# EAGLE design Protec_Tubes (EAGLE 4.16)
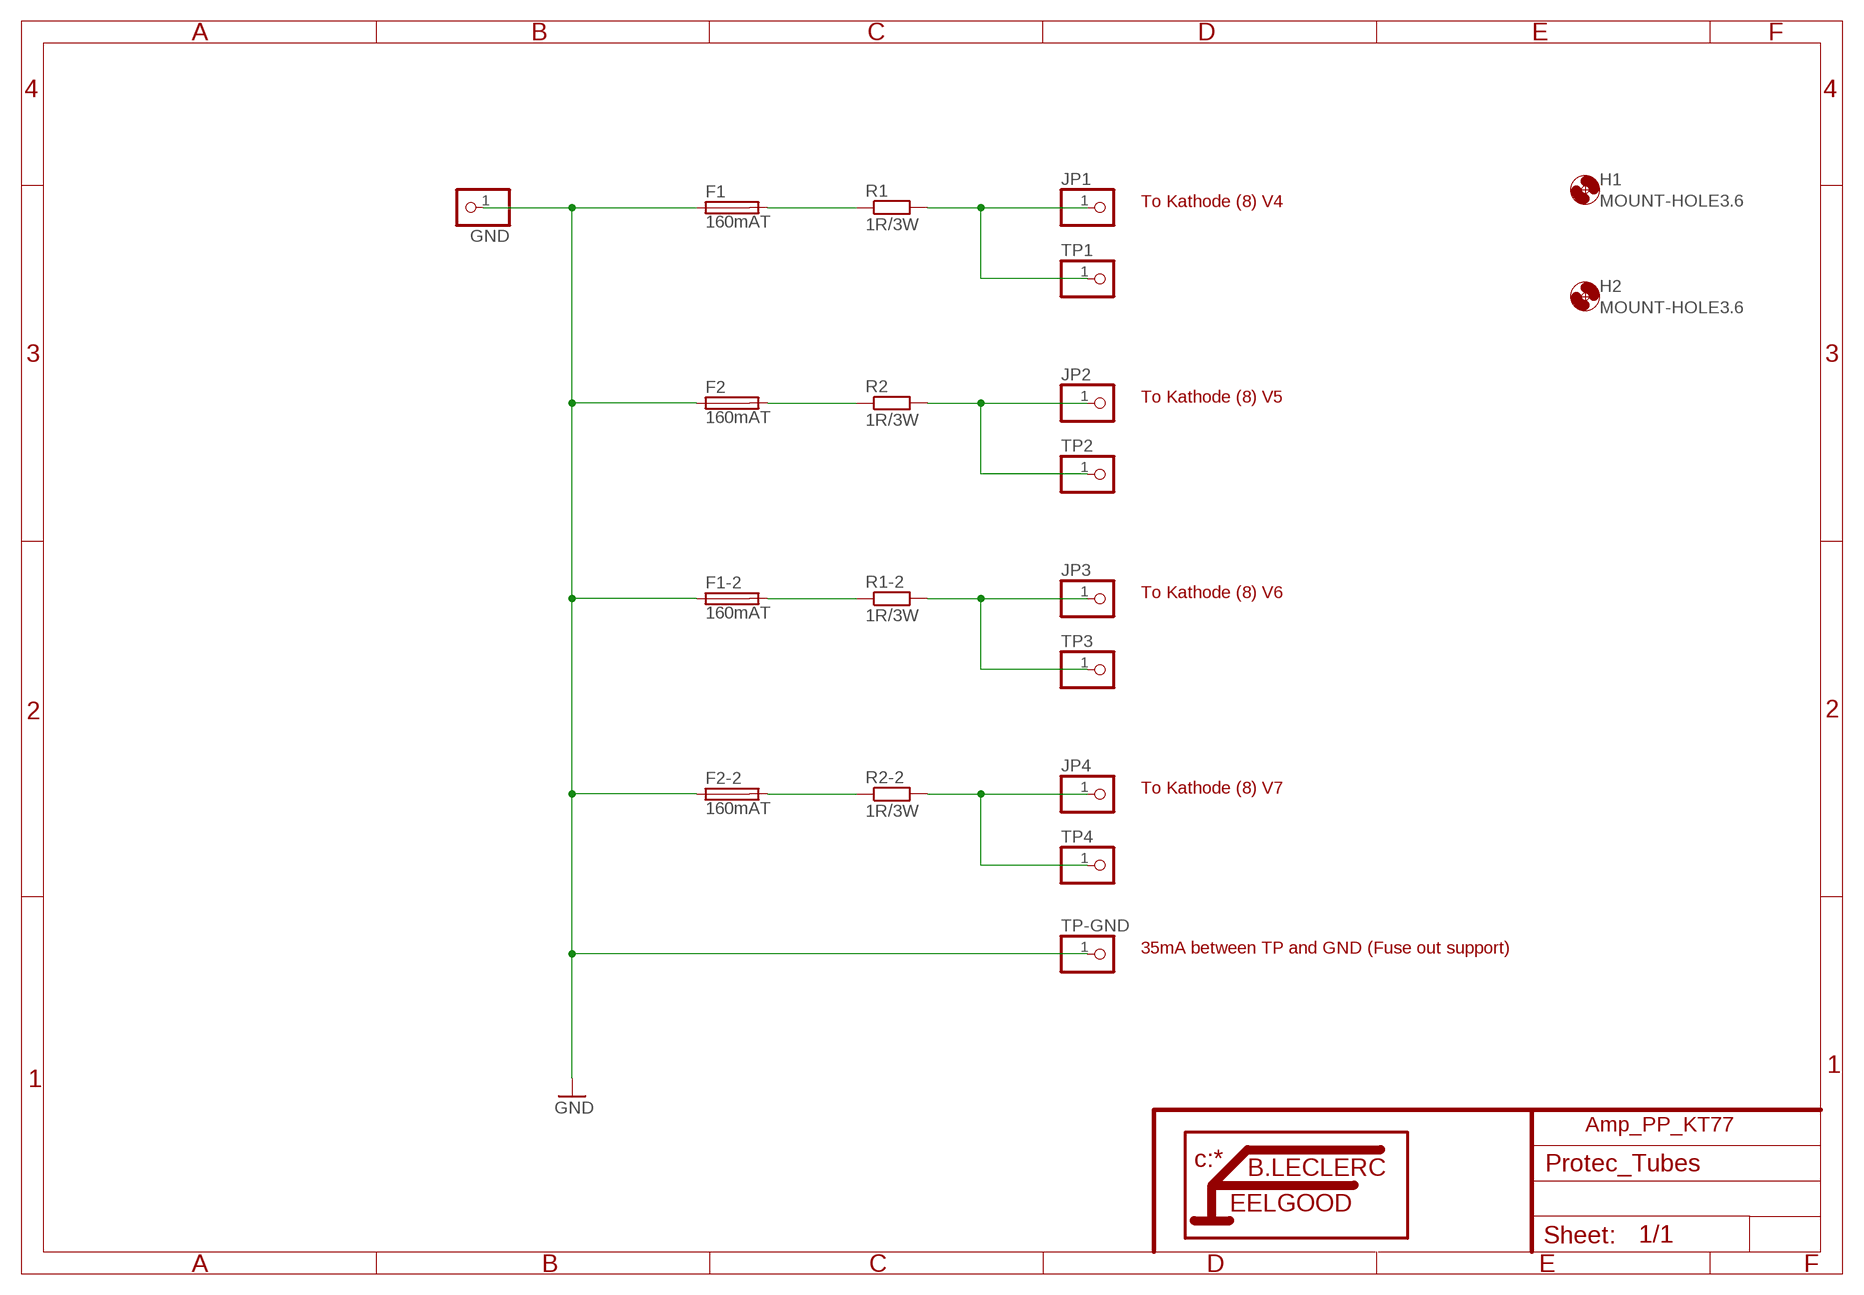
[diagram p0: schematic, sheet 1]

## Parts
F1  160mAT  FUSESH22,5  [SH22,5]
F1-2  160mAT  FUSESH22,5  [SH22,5]
F2  160mAT  FUSESH22,5  [SH22,5]
F2-2  160mAT  FUSESH22,5  [SH22,5]
GND  PINHD-1X1  [1X01]
H1  MOUNT-HOLE3.6  [3,6]
H2  MOUNT-HOLE3.6  [3,6]
JP1  PINHD-1X1  [1X01]
JP2  PINHD-1X1  [1X01]
JP3  PINHD-1X1  [1X01]
JP4  PINHD-1X1  [1X01]
R1  1R/3W  R-EU_0617/22  [0617/22]
R1-2  1R/3W  R-EU_0617/22  [0617/22]
R2  1R/3W  R-EU_0617/22  [0617/22]
R2-2  1R/3W  R-EU_0617/22  [0617/22]
TP1  PINHD-1X1  [1X01]
TP2  PINHD-1X1  [1X01]
TP3  PINHD-1X1  [1X01]
TP4  PINHD-1X1  [1X01]
TP-GND  PINHD-1X1  [1X01]

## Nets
GND: F1-2.1 F1.1 F2-2.1 F2.1 GND.1 TP-GND.1
N$2: F1.2 R1.1
N$3: F2.2 R2.1
N$4: F1-2.2 R1-2.1
N$5: F2-2.2 R2-2.1
N$6: JP1.1 R1.2 TP1.1
N$7: JP2.1 R2.2 TP2.1
N$8: JP3.1 R1-2.2 TP3.1
N$9: JP4.1 R2-2.2 TP4.1

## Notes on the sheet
- To Kathode (8) V4
- To Kathode (8) V5
- To Kathode (8) V6
- To Kathode (8) V7
- 35mA between TP and GND (Fuse out support)
- Amp_PP_KT77

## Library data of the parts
F1 F1-2 F2 F2-2 = fuse:FUSE: Fuse
GND JP1-JP4 TP1-TP4 TP-GND = pinhead:PINHD-1X1: PIN HEADER
H1 H2 = holes:MOUNT-HOLE: MOUNTING HOLE with drill center marker
R1 R1-2 R2 R2-2 = rcl:R-EU_: RESISTOR, European symbol

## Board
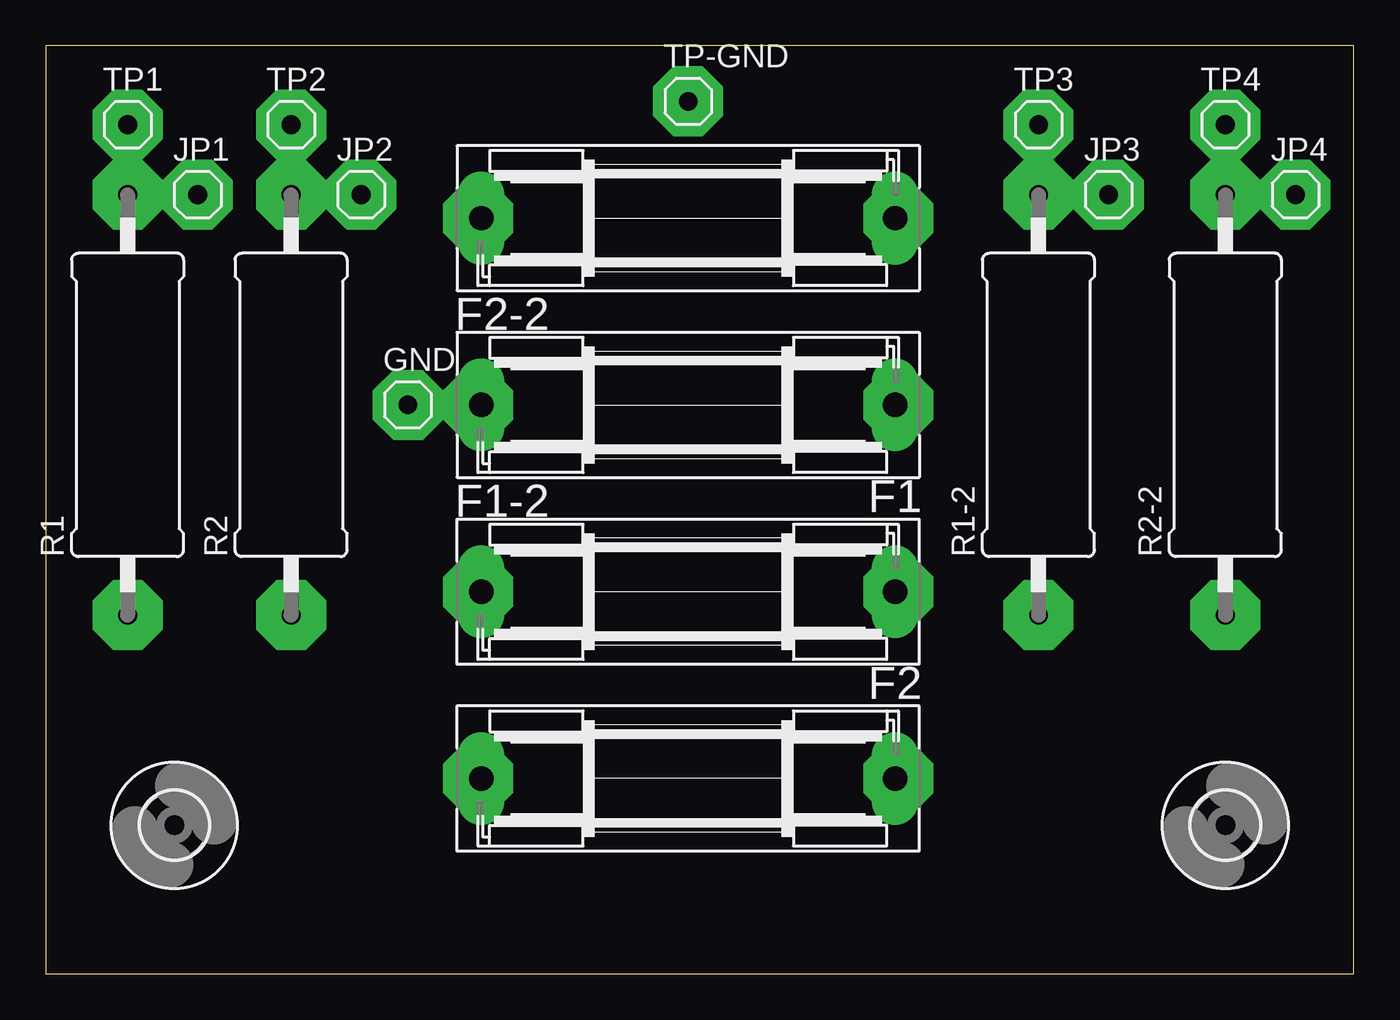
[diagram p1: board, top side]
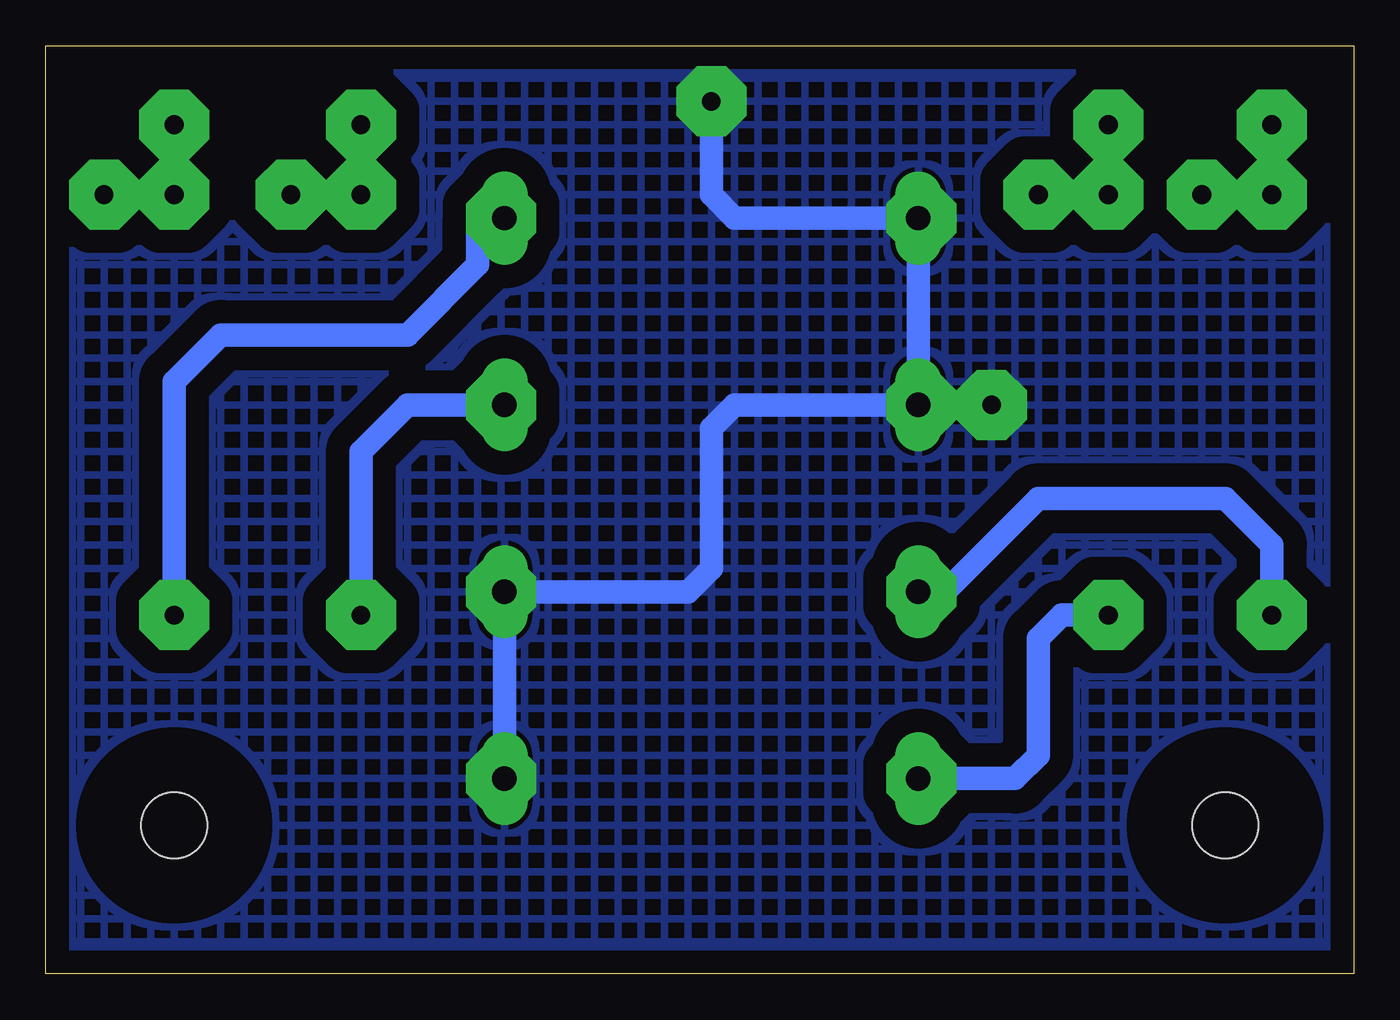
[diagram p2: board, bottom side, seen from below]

Size 71.1 x 50.47 mm. Coordinates in mm from the lower left corner, seen from the top.
Outline: 0,0 71.1,0 71.1,50.47 0,50.47 0,0
Copper layers (1*16): Top 0.035mm / dielectric 1.5mm / Bottom 0.035mm
Design rules "default": minimum track width 10mil, minimum drill 24mil, track to track 8mil, track to pad 8mil, pad to pad 8mil, via to via 8mil, smd to smd 8mil, copper to edge 40mil, drill to drill 8mil, minimum pad ring 10mil, minimum via ring 8mil, stop-mask expansion 4mil, vias tented up to drill 0mil, thermal gap 10mil

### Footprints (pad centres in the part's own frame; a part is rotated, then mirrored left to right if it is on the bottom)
SH22,5 = drill 1.321 pad 2.54 long: 1 -11.252,0; 2 11.252,0
1X01 = drill 1.016 octagon: 1 0,0
3,6 = hole 3.6: 0,0
0617/22 = drill 1.016 octagon: 1 -11.43,0; 2 11.43,0

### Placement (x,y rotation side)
F1  34.92,20.79 180 top
F1-2  34.92,30.95 0 top
F2  34.92,10.63 180 top
F2-2  34.92,41.11 0 top
GND  19.68,30.95 0 top
H1  64.13,8.09 0 top
H2  6.98,8.09 0 top
JP1  8.25,42.38 0 top
JP2  17.14,42.38 0 top
JP3  57.78,42.38 0 top
JP4  67.94,42.38 0 top
R1  4.44,30.95 90 top
R1-2  53.97,30.95 90 top
R2  13.33,30.95 90 top
R2-2  64.13,30.95 90 top
TP1  4.44,46.19 0 top
TP2  13.33,46.19 0 top
TP3  53.97,46.19 0 top
TP4  64.13,46.19 0 top
TP-GND  34.92,47.46 0 top

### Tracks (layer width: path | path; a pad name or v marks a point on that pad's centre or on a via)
GND  (via drill 0.5 pad 3.81)
  Bottom 1.27: TP-GND.1 34.92,42.38 33.65,41.11 F2-2.1 | F2-2.1 v23.49,41.11 | GND.1 v23.49,30.95 | v23.49,30.95 F1-2.1 33.65,30.95 34.92,29.68 34.92,22.06 36.19,20.79 F1.1 | F2-2.1 23.67,31.13 v23.49,30.95 | F1.1 v46.35,20.79 | F2.1 v46.35,10.63 46.17,10.81 F1.1
  other vias: 34.92,47.46 19.68,30.95
  pour Bottom (isolate 1.27, hatched): 0.63,50 70.48,50 70.48,0.47 0.63,0.47
N$1  (via drill 0.5 pad 3.81)
  other vias: 64.13,46.19
N$2
  Bottom 1.27: R1.1 4.44,23.33 6.98,25.87 17.14,25.87 22.22,20.79 F1.2
N$3
  Bottom 1.27: R2.1 15.87,19.52 17.14,18.25 17.14,11.9 18.41,10.63 F2.2
N$4
  Bottom 1.27: F1-2.2 51.43,30.95 53.97,28.41 R1-2.1
N$5
  Bottom 1.27: F2-2.2 47.62,41.11 47.62,38.57 51.43,34.76 61.59,34.76 64.13,32.22 R2-2.1
N$6
  Bottom 1.27: TP1.1 R1.2 JP1.1
N$7
  Bottom 1.27: TP2.1 R2.2 JP2.1
N$8
  Bottom 1.27: TP3.1 R1-2.2 JP3.1
N$9
  Bottom 1.27: TP4.1 R2-2.2 JP4.1
N$10  (via drill 0.5 pad 3.81)
  other vias: 67.94,42.38
N$12  (via drill 0.5 pad 3.81)
  other vias: 53.97,19.52
N$13  (via drill 0.5 pad 3.81)
  other vias: 13.33,42.38
N$14  (via drill 0.5 pad 3.81)
  other vias: 8.25,42.38
N$16  (via drill 0.5 pad 3.81)
  other vias: 13.33,46.19
N$17  (via drill 0.5 pad 3.81)
  other vias: 4.44,46.19
N$18  (via drill 0.5 pad 3.81)
  other vias: 53.97,46.19
N$19  (via drill 0.5 pad 3.81)
  other vias: 4.44,42.38
N$20  (via drill 0.5 pad 3.81)
  other vias: 17.14,42.38
N$21  (via drill 0.5 pad 3.81)
  other vias: 57.78,42.38
N$22  (via drill 0.5 pad 3.81)
  other vias: 53.97,42.38
N$23  (via drill 0.5 pad 3.81)
  other vias: 4.44,19.52
N$24  (via drill 0.5 pad 3.81)
  other vias: 13.33,19.52
N$26  (via drill 0.5 pad 3.81)
  other vias: 46.35,41.11
N$27  (via drill 0.5 pad 3.81)
  other vias: 46.35,30.95
N$29  (via drill 0.5 pad 3.81)
  other vias: 23.49,20.79
N$30  (via drill 0.5 pad 3.81)
  other vias: 64.13,42.38
N$32  (via drill 0.5 pad 3.81)
  other vias: 64.13,19.52
N$33  (via drill 0.5 pad 3.81)
  other vias: 23.49,10.63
